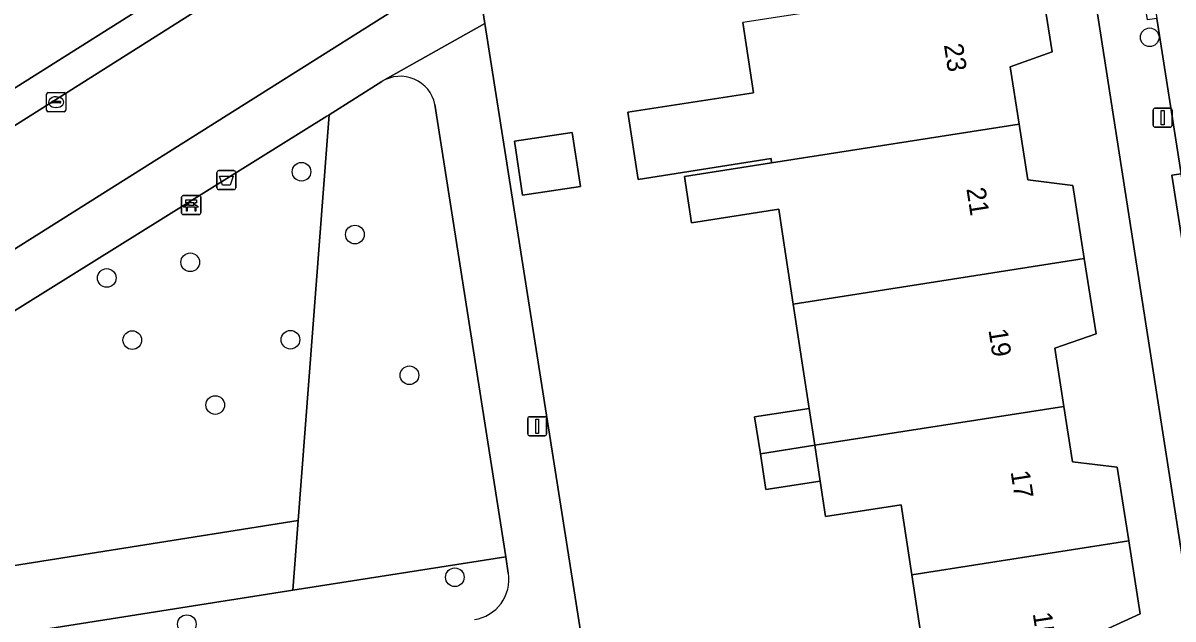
# Model space of a CAD drawing. Extents: x 160077 to 160948, y 386481 to 387498.
# Drawn here: x 160484.1 to 160544.4, y 387208.7 to 387240 of the extents above; entities that cross this region are included whole.
import ezdxf

# ---------------------------------------------------------------- set-up
doc = ezdxf.new("R2010")
doc.units = 0
for name, color, linetype in [('IMGEO_Afvalbak', 7, 'Continuous'), ('IMGEO_Bank', 7, 'Continuous'), ('IMGEO_Boom', 7, 'Continuous'), ('IMGEO_Erf', 7, 'Continuous'), ('IMGEO_Groenvoorziening', 7, 'Continuous'), ('IMGEO_Kolk', 7, 'Continuous'), ('IMGEO_Lichtmast', 7, 'Continuous'), ('IMGEO_Pand', 7, 'Continuous'), ('IMGEO_Pand_nummerreeks', 7, 'Continuous'), ('IMGEO_Parkeervlak_open', 7, 'Continuous'), ('IMGEO_Rijbaan_lokaal_gesloten', 7, 'Continuous'), ('IMGEO_Rijbaan_lokaal_open', 7, 'Continuous'), ('IMGEO_Voetpad_open', 7, 'Continuous')]:
    doc.layers.add(name, color=color, linetype=linetype)

msp = doc.modelspace()

# ---------------------------------------------------------------- linework, layer by layer
at = {"layer": 'IMGEO_Afvalbak'}
for p, q in [((160494.234, 387231.332), (160494.234, 387232.132)), ((160494.234, 387232.132), (160494.234, 387231.332)), ((160494.334, 387232.232), (160495.124, 387232.232)), ((160495.124, 387232.232), (160494.334, 387232.232)), ((160495.224, 387232.132), (160495.224, 387231.332)), ((160495.224, 387231.332), (160495.224, 387232.132)), ((160495.124, 387231.232), (160494.334, 387231.232)), ((160494.334, 387231.232), (160495.124, 387231.232))]:
    msp.add_line(p, q, dxfattribs=at)
msp.add_lwpolyline([(160494.377, 387231.946), (160495.081, 387231.946), (160494.932, 387231.476), (160494.526, 387231.476), (160494.377, 387231.946)], dxfattribs=at)
for centre, start, end in [((160494.334, 387232.132), 90, 180), ((160494.334, 387232.132), 90, 180), ((160495.124, 387232.132), 0, 90), ((160495.124, 387232.132), 360, 90), ((160494.334, 387231.332), 180, 270), ((160494.334, 387231.332), 180, 270), ((160495.124, 387231.332), 270, 0), ((160495.124, 387231.332), 270, 0)]:
    msp.add_arc(centre, 0.1, start, end, dxfattribs=at)
at = {"layer": 'IMGEO_Bank'}
for p, q in [((160492.384, 387229.999), (160492.384, 387230.84)), ((160492.384, 387230.84), (160492.384, 387229.999)), ((160492.459, 387230.924), (160493.3, 387230.924)), ((160493.3, 387230.924), (160492.459, 387230.924)), ((160493.384, 387230.849), (160493.384, 387230.008)), ((160493.384, 387230.008), (160493.384, 387230.849)), ((160493.081, 387230.322), (160492.688, 387230.322)), ((160492.693, 387230.43), (160492.693, 387230.536)), ((160492.737, 387230.536), (160492.737, 387230.43)), ((160493.025, 387230.542), (160492.743, 387230.542)), ((160492.743, 387230.424), (160493.025, 387230.424)), ((160493.031, 387230.43), (160493.031, 387230.536)), ((160493.075, 387230.536), (160493.075, 387230.43)), ((160493.309, 387229.924), (160492.468, 387229.924)), ((160492.468, 387229.924), (160493.309, 387229.924))]:
    msp.add_line(p, q, dxfattribs=at)
for points in [[(160492.687, 387230.542), (160492.601, 387230.542), (160492.601, 387230.703), (160493.164, 387230.703), (160493.164, 387230.542), (160493.081, 387230.542)], [(160492.631, 387230.322), (160492.489, 387230.322), (160492.601, 387230.424), (160492.687, 387230.424)], [(160492.681, 387230.315), (160492.681, 387230.108), (160492.638, 387230.108), (160492.638, 387230.315)], [(160493.081, 387230.424), (160493.164, 387230.424), (160493.276, 387230.322), (160493.137, 387230.322)], [(160493.131, 387230.315), (160493.131, 387230.108), (160493.087, 387230.108), (160493.087, 387230.315)]]:
    msp.add_lwpolyline(points, dxfattribs=at)
for centre, radius, start, end in [((160492.462, 387230.846), 0.0779, 92.4484, 184.28452), ((160492.462, 387230.846), 0.0779, 92.4484, 184.28452), ((160493.306, 387230.846), 0.0779, 2.4484, 94.28452), ((160493.306, 387230.846), 0.0779, 2.4484, 94.28452), ((160492.462, 387230.002), 0.0779, 182.4484, 274.28452), ((160492.462, 387230.002), 0.0779, 182.4484, 274.28452), ((160492.631, 387230.315), 0.00671, 2.89567, 87.10433), ((160492.688, 387230.315), 0.00671, 92.89567, 177.10433), ((160492.686, 387230.535), 0.00671, 2.89567, 87.10433), ((160492.686, 387230.431), 0.00671, 272.89567, 357.10433), ((160492.743, 387230.535), 0.00671, 92.89567, 177.10433), ((160492.743, 387230.431), 0.00671, 182.89567, 267.10433), ((160493.025, 387230.535), 0.00671, 2.89567, 87.10433), ((160493.025, 387230.431), 0.00671, 272.89567, 357.10433), ((160493.082, 387230.535), 0.00671, 92.89567, 177.10433), ((160493.082, 387230.431), 0.00671, 182.89567, 267.10433), ((160493.08, 387230.315), 0.00671, 2.89567, 87.10433), ((160493.137, 387230.315), 0.00671, 92.89567, 177.10433), ((160493.306, 387230.002), 0.0779, 272.4484, 4.28452), ((160493.306, 387230.002), 0.0779, 272.4484, 4.28452)]:
    msp.add_arc(centre, radius, start, end, dxfattribs=at)
at = {"layer": 'IMGEO_Boom'}
for centre in [(160543.134, 387239.226), (160498.667, 387232.172), (160501.467, 387228.877), (160492.836, 387227.421), (160488.458, 387226.598), (160489.797, 387223.337), (160498.087, 387223.357), (160504.325, 387221.493), (160494.146, 387219.931), (160506.707, 387210.894), (160492.657, 387208.434)]:
    msp.add_circle(centre, 0.489, dxfattribs=at)
at = {"layer": 'IMGEO_Erf'}
for points in [[(160553.452, 387156.678), (160538.915, 387250)], [(160507.612, 387244.225), (160508.282, 387239.959), (160513.55, 387206.404)], [(160537.395, 387242.436), (160538.015, 387238.47), (160535.817, 387237.673), (160536.286, 387234.673), (160536.743, 387231.753), (160539.107, 387231.445), (160539.706, 387227.618), (160540.324, 387223.667), (160538.158, 387222.912), (160538.635, 387219.861), (160539.088, 387216.959), (160541.426, 387216.679), (160542.032, 387212.801), (160542.63, 387208.977), (160540.529, 387208.007)], [(160531.221, 387207.335), (160530.659, 387211.023), (160530.1, 387214.69), (160526.145, 387214.087), (160525.863, 387215.938), (160523.017, 387215.492), (160522.723, 387217.372), (160522.42, 387219.306), (160525.281, 387219.754), (160525.005, 387221.561), (160524.445, 387225.232), (160523.883, 387228.916), (160523.686, 387230.21), (160519.119, 387229.496), (160518.748, 387231.93), (160523.315, 387232.644), (160523.282, 387232.859), (160516.313, 387231.77), (160515.775, 387235.296), (160522.361, 387236.311), (160521.799, 387239.997)]]:
    msp.add_lwpolyline(points, dxfattribs=at)
msp.add_lwpolyline([(160512.866, 387234.227), (160513.291, 387231.401), (160510.251, 387230.945), (160509.826, 387233.771)], close=True, dxfattribs=at)
at = {"layer": 'IMGEO_Groenvoorziening'}
for points in [[(160502.873, 387236.9), (160500.121, 387235.16), (160500, 387233.575), (160498.497, 387213.871), (160498.218, 387210.216), (160509.377, 387211.966), (160505.663, 387235.704)], [(160509.511, 387211.109), (160509.377, 387211.966), (160498.218, 387210.216), (160471.06, 387205.939), (160448.92, 387202.55)]]:
    msp.add_lwpolyline(points, dxfattribs=at)
for points in [[(160500, 387233.575), (160500.121, 387235.16), (160500, 387235.084), (160465.938, 387213.851), (160468.963, 387209.178), (160498.497, 387213.871)], [(160471.06, 387205.939), (160498.218, 387210.216), (160498.497, 387213.871), (160468.963, 387209.178)]]:
    msp.add_lwpolyline(points, close=True, dxfattribs=at)
for centre, radius, start, end in [((160503.853, 387235.334), 1.847, 11.54896, 122.04394), ((160507.405, 387210.779), 2.132, 278.86125, 8.91085)]:
    msp.add_arc(centre, radius, start, end, dxfattribs=at)
at = {"layer": 'IMGEO_Kolk'}
for p, q in [((160485.305, 387235.398), (160485.305, 387236.25)), ((160485.38, 387236.324), (160486.232, 387236.324)), ((160485.793, 387236.104), (160485.818, 387236.104)), ((160486.306, 387236.25), (160486.306, 387235.398)), ((160485.564, 387235.818), (160485.564, 387235.83)), ((160486.002, 387235.781), (160485.604, 387235.781)), ((160485.607, 387235.867), (160486.005, 387235.867)), ((160485.816, 387235.544), (160485.791, 387235.544)), ((160486.048, 387235.83), (160486.048, 387235.818)), ((160486.232, 387235.324), (160485.38, 387235.324))]:
    msp.add_line(p, q, dxfattribs=at)
for points in [[(160485.305, 387235.398), (160485.305, 387236.25)], [(160485.38, 387236.324), (160486.232, 387236.324)], [(160486.306, 387236.25), (160486.306, 387235.398)], [(160486.232, 387235.324), (160485.38, 387235.324)]]:
    msp.add_lwpolyline(points, dxfattribs=at)
for centre, radius, start, end in [((160485.382, 387236.248), 0.0765, 91.55205, 178.44795), ((160485.382, 387236.248), 0.0765, 91.55205, 178.44795), ((160486.23, 387236.248), 0.0765, 1.55205, 88.44795), ((160486.23, 387236.248), 0.0765, 1.55205, 88.44795), ((160485.382, 387235.4), 0.0765, 181.55205, 268.44795), ((160485.382, 387235.4), 0.0765, 181.55205, 268.44795), ((160485.604, 387235.827), 0.0403, 85.87752, 175.75265), ((160485.601, 387235.817), 0.0366, 178.93798, 274.71019), ((160486.005, 387235.824), 0.043, 264.86636, 352.45326), ((160486.009, 387235.829), 0.0386, 1.73085, 96.63898), ((160486.23, 387235.4), 0.0765, 271.55205, 358.44795), ((160486.23, 387235.4), 0.0765, 271.55205, 358.44795)]:
    msp.add_arc(centre, radius, start, end, dxfattribs=at)
for centre, major_axis, ratio, start_param, end_param in [((160485.792, 387235.824), (-0.387, 0.002), 0.722429, 4.712389, 7.853982), ((160485.817, 387235.824), (-0.39, 0.002), 0.717154, 1.570796, 4.712389)]:
    msp.add_ellipse(centre, major_axis=major_axis, ratio=ratio, start_param=start_param, end_param=end_param, dxfattribs=at)
at = {"layer": 'IMGEO_Lichtmast'}
for p, q in [((160543.316, 387234.611), (160543.316, 387235.411)), ((160543.316, 387235.411), (160543.316, 387234.611)), ((160543.416, 387235.511), (160544.206, 387235.511)), ((160544.206, 387235.511), (160543.416, 387235.511)), ((160544.306, 387235.411), (160544.306, 387234.611)), ((160544.306, 387234.611), (160544.306, 387235.411)), ((160544.206, 387234.511), (160543.416, 387234.511)), ((160543.416, 387234.511), (160544.206, 387234.511)), ((160510.528, 387218.416), (160510.528, 387219.216)), ((160510.528, 387219.216), (160510.528, 387218.416)), ((160510.628, 387219.316), (160511.418, 387219.316)), ((160511.418, 387219.316), (160510.628, 387219.316)), ((160511.518, 387219.216), (160511.518, 387218.416)), ((160511.518, 387218.416), (160511.518, 387219.216)), ((160511.418, 387218.316), (160510.628, 387218.316)), ((160510.628, 387218.316), (160511.418, 387218.316))]:
    msp.add_line(p, q, dxfattribs=at)
for points in [[(160543.736, 387235.386), (160543.886, 387235.386), (160543.886, 387234.636), (160543.736, 387234.636), (160543.736, 387235.386)], [(160510.948, 387219.191), (160511.098, 387219.191), (160511.098, 387218.441), (160510.948, 387218.441), (160510.948, 387219.191)]]:
    msp.add_lwpolyline(points, dxfattribs=at)
for centre, start, end in [((160543.416, 387235.411), 90, 180), ((160543.416, 387235.411), 90, 180), ((160544.206, 387235.411), 0, 90), ((160544.206, 387235.411), 360, 90), ((160543.416, 387234.611), 180, 270), ((160543.416, 387234.611), 180, 270), ((160544.206, 387234.611), 270, 0), ((160544.206, 387234.611), 270, 0), ((160510.628, 387219.216), 90, 180), ((160510.628, 387219.216), 90, 180), ((160511.418, 387219.216), 0, 90), ((160511.418, 387219.216), 360, 90), ((160510.628, 387218.416), 180, 270), ((160510.628, 387218.416), 180, 270), ((160511.418, 387218.416), 270, 0), ((160511.418, 387218.416), 270, 0)]:
    msp.add_arc(centre, 0.1, start, end, dxfattribs=at)
at = {"layer": 'IMGEO_Pand'}
for points in [[(160538.015, 387238.47), (160537.395, 387242.436), (160526.138, 387240.676), (160521.799, 387239.997), (160522.361, 387236.311), (160515.775, 387235.296), (160516.313, 387231.77), (160523.282, 387232.859), (160523.315, 387232.644), (160536.286, 387234.673), (160535.817, 387237.673)], [(160509.826, 387233.771), (160510.251, 387230.945), (160513.291, 387231.401), (160512.866, 387234.227)], [(160539.706, 387227.618), (160539.107, 387231.445), (160536.743, 387231.753), (160536.286, 387234.673), (160523.315, 387232.644), (160518.748, 387231.93), (160519.119, 387229.496), (160523.686, 387230.21), (160523.883, 387228.916), (160524.445, 387225.232)], [(160538.158, 387222.912), (160540.324, 387223.667), (160539.706, 387227.618), (160524.445, 387225.232), (160525.005, 387221.561), (160525.281, 387219.754), (160525.576, 387217.818), (160538.635, 387219.861)], [(160525.281, 387219.754), (160522.42, 387219.306), (160522.723, 387217.372), (160525.576, 387217.818)], [(160541.426, 387216.679), (160539.088, 387216.959), (160538.635, 387219.861), (160525.576, 387217.818), (160525.863, 387215.938), (160526.145, 387214.087), (160530.1, 387214.69), (160530.659, 387211.023), (160542.032, 387212.801)], [(160525.576, 387217.818), (160522.723, 387217.372), (160523.017, 387215.492), (160525.863, 387215.938)], [(160540.529, 387208.007), (160542.63, 387208.977), (160542.032, 387212.801), (160530.659, 387211.023), (160531.221, 387207.335), (160527.266, 387206.732), (160527.538, 387204.945), (160527.836, 387202.992), (160540.992, 387205.05)]]:
    msp.add_lwpolyline(points, close=True, dxfattribs=at)
at = {"layer": 'IMGEO_Parkeervlak_open'}
for points in [[(160501.954, 387246.167), (160494.536, 387241.499), (160493.712, 387240.972), (160478.021, 387231.045), (160477.162, 387230.526), (160467.409, 387224.394), (160449.009, 387212.798)], [(160452.917, 387208.765), (160497.878, 387237.096), (160503.883, 387240.878)]]:
    msp.add_lwpolyline(points, dxfattribs=at)
at = {"layer": 'IMGEO_Rijbaan_lokaal_gesloten'}
msp.add_lwpolyline([(160493.712, 387240.972), (160492.831, 387242.374), (160477.128, 387232.473), (160478.021, 387231.045)], close=True, dxfattribs=at)
at = {"layer": 'IMGEO_Rijbaan_lokaal_open'}
for points in [[(160541.909, 387250), (160542.279, 387248.083), (160542.579, 387246.171), (160543.513, 387240.213), (160544.791, 387232.064)], [(160475.088, 387235.715), (160477.128, 387232.473), (160492.831, 387242.374)]]:
    msp.add_lwpolyline(points, dxfattribs=at)
at = {"layer": 'IMGEO_Voetpad_open'}
for points in [[(160538.915, 387250), (160553.452, 387156.678), (160553.93, 387153.57)], [(160548.152, 387210.65), (160547.658, 387210.574), (160546.592, 387217.352), (160547.086, 387217.428), (160545.87, 387225.181), (160545.376, 387225.104), (160544.297, 387231.987), (160544.791, 387232.064), (160543.513, 387240.213), (160543.019, 387240.137), (160542.085, 387246.095), (160542.579, 387246.171), (160542.279, 387248.083), (160541.909, 387250)], [(160465.938, 387213.851), (160500, 387235.084), (160500.121, 387235.16), (160502.873, 387236.9), (160502.892, 387236.932), (160508.282, 387239.959), (160507.612, 387244.225)], [(160503.883, 387240.878), (160497.878, 387237.096), (160452.917, 387208.765)], [(160485.133, 387201.848), (160486.443, 387202.053), (160500, 387204.183), (160508.597, 387205.531), (160513.55, 387206.404), (160508.282, 387239.959), (160502.892, 387236.932), (160502.873, 387236.9)], [(160505.663, 387235.704), (160509.377, 387211.966), (160509.511, 387211.109)]]:
    msp.add_lwpolyline(points, dxfattribs=at)
msp.add_lwpolyline([(160544.791, 387232.064), (160544.297, 387231.987), (160545.376, 387225.104), (160545.87, 387225.181)], close=True, dxfattribs=at)
for centre, radius, start, end in [((160503.853, 387235.334), 1.847, 11.54896, 122.04394), ((160507.405, 387210.779), 2.132, 278.86125, 8.91085)]:
    msp.add_arc(centre, radius, start, end, dxfattribs=at)

# ---------------------------------------------------------------- texts
at = {"layer": 'IMGEO_Pand_nummerreeks'}
for s, rotation, p in [('23', 278.86918, (160532.343, 387238.829)), ('21', 278.86836, (160533.52, 387231.283)), ('19', 278.86918, (160534.678, 387223.867)), ('17', 278.86918, (160535.838, 387216.431)), ('15', 278.86918, (160536.998, 387208.994))]:
    msp.add_text(s, height=1, rotation=rotation, dxfattribs=at).set_placement(p)

doc.saveas('drawing.dxf')
